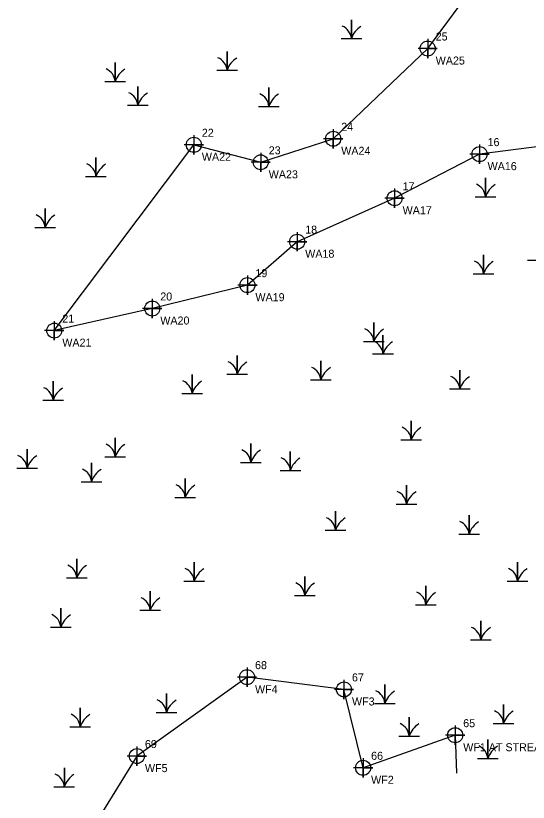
# Model space of a CAD drawing. Extents: x 2189822 to 2190837, y 387253 to 388663.
# Drawn here: x 2190174.5 to 2190334.4, y 387891.4 to 388136.9 of the extents above; entities that cross this region are included whole.
import ezdxf

# ---------------------------------------------------------------- set-up
doc = ezdxf.new("R2010")
doc.units = 0
for name, color, linetype in [('COGO Default Chain', 7, 'Continuous'), ('DTM Contours Major', 7, 'Continuous'), ('DTM Contours Minor', 7, 'Continuous'), ('Exist DTM Breakline Cogo Elevation', 7, 'Continuous'), ('Exist DTM Breakline Cogo Number', 7, 'Continuous')]:
    doc.layers.add(name, color=color, linetype=linetype)

msp = doc.modelspace()

# ---------------------------------------------------------------- linework, layer by layer
at = {"layer": 'DTM Contours Major'}
for points in [[(2190303.02, 388129.66), (2190303.02, 388123.66), (2190303.02, 388126.66), (2190306.02, 388126.66), (2190300.02, 388126.66)], [(2190273.55, 388101.49), (2190273.55, 388095.49), (2190273.55, 388098.49), (2190276.55, 388098.49), (2190270.55, 388098.49)], [(2190230.07, 388099.61), (2190230.07, 388093.61), (2190230.07, 388096.61), (2190233.07, 388096.61), (2190227.07, 388096.61)], [(2190319.2, 388096.69), (2190319.2, 388090.69), (2190319.2, 388093.69), (2190322.2, 388093.69), (2190316.2, 388093.69)], [(2190250.93, 388094.14), (2190250.93, 388088.14), (2190250.93, 388091.14), (2190253.93, 388091.14), (2190247.93, 388091.14)], [(2190292.7, 388082.93), (2190292.7, 388076.93), (2190292.7, 388079.93), (2190295.7, 388079.93), (2190289.7, 388079.93)], [(2190262.31, 388069.36), (2190262.31, 388063.36), (2190262.31, 388066.36), (2190265.31, 388066.36), (2190259.31, 388066.36)], [(2190246.78, 388055.8), (2190246.78, 388049.8), (2190246.78, 388052.8), (2190249.78, 388052.8), (2190243.78, 388052.8)], [(2190217.1, 388048.51), (2190217.1, 388042.51), (2190217.1, 388045.51), (2190220.1, 388045.51), (2190214.1, 388045.51)], [(2190186.53, 388041.61), (2190186.53, 388035.61), (2190186.53, 388038.61), (2190189.53, 388038.61), (2190183.53, 388038.61)], [(2190246.66, 387933.44), (2190246.66, 387927.44), (2190246.66, 387930.44), (2190249.66, 387930.44), (2190243.66, 387930.44)], [(2190276.9, 387929.61), (2190276.9, 387923.61), (2190276.9, 387926.61), (2190279.9, 387926.61), (2190273.9, 387926.61)], [(2190311.6, 387915.32), (2190311.6, 387909.32), (2190311.6, 387912.32), (2190314.6, 387912.32), (2190308.6, 387912.32)], [(2190212.31, 387908.81), (2190212.31, 387902.81), (2190212.31, 387905.81), (2190215.31, 387905.81), (2190209.31, 387905.81)], [(2190282.87, 387905.15), (2190282.87, 387899.15), (2190282.87, 387902.15), (2190285.87, 387902.15), (2190279.87, 387902.15)]]:
    msp.add_lwpolyline(points, dxfattribs=at)
for centre in [(2190303.02, 388126.66), (2190273.55, 388098.49), (2190230.07, 388096.61), (2190319.2, 388093.69), (2190250.93, 388091.14), (2190292.7, 388079.93), (2190262.31, 388066.36), (2190246.78, 388052.8), (2190217.1, 388045.51), (2190186.53, 388038.61), (2190246.66, 387930.44), (2190276.9, 387926.61), (2190311.6, 387912.32), (2190212.31, 387905.81), (2190282.87, 387902.15)]:
    msp.add_circle(centre, 2.34, dxfattribs=at)
at = {"layer": 'Exist DTM Breakline Cogo Elevation'}
for p, q in [((2190279.21, 388132.42), (2190279.21, 388132.42)), ((2190240.43, 388122.54), (2190240.43, 388122.54)), ((2190205.53, 388119.01), (2190205.53, 388119.01)), ((2190212.58, 388111.61), (2190212.58, 388111.61)), ((2190253.47, 388111.25), (2190253.47, 388111.25)), ((2190199.54, 388089.38), (2190199.54, 388089.38)), ((2190321.04, 388083.01), (2190321.04, 388083.01)), ((2190183.67, 388073.51), (2190183.67, 388073.51)), ((2190320.45, 388059.05), (2190320.45, 388059.05)), ((2190286.26, 388037.88), (2190286.26, 388037.88)), ((2190289.08, 388034), (2190289.08, 388034)), ((2190243.6, 388027.65), (2190243.6, 388027.65)), ((2190269.69, 388025.89), (2190269.69, 388025.89)), ((2190229.5, 388021.65), (2190229.5, 388021.65)), ((2190313.05, 388023.06), (2190313.05, 388023.06)), ((2190186.14, 388019.54), (2190186.14, 388019.54)), ((2190297.89, 388007.19), (2190297.89, 388007.19)), ((2190205.53, 388001.9), (2190205.53, 388001.9)), ((2190247.83, 388000.14), (2190247.83, 388000.14)), ((2190178.03, 387998.37), (2190178.03, 387998.37)), ((2190260.17, 387997.67), (2190260.17, 387997.67)), ((2190198.13, 387994.14), (2190198.13, 387994.14)), ((2190227.39, 387989.2), (2190227.39, 387989.2)), ((2190296.38, 387987.14), (2190296.38, 387987.14)), ((2190274.27, 387978.97), (2190274.27, 387978.97)), ((2190315.92, 387977.8), (2190315.92, 387977.8)), ((2190193.55, 387964.16), (2190193.55, 387964.16)), ((2190230.21, 387963.1), (2190230.21, 387963.1)), ((2190331.03, 387963.1), (2190331.03, 387963.1)), ((2190264.7, 387958.62), (2190264.7, 387958.62)), ((2190302.48, 387955.69), (2190302.48, 387955.69)), ((2190216.46, 387953.99), (2190216.46, 387953.99)), ((2190188.57, 387948.7), (2190188.57, 387948.7)), ((2190319.56, 387944.74), (2190319.56, 387944.74)), ((2190289.68, 387924.9), (2190289.68, 387924.9)), ((2190221.51, 387922.07), (2190221.51, 387922.07)), ((2190326.69, 387918.67), (2190326.69, 387918.67)), ((2190194.6, 387917.59), (2190194.6, 387917.59)), ((2190297.23, 387914.7), (2190297.23, 387914.7)), ((2190321.78, 387907.71), (2190321.78, 387907.71)), ((2190189.67, 387898.9), (2190189.67, 387898.9))]:
    msp.add_line(p, q, dxfattribs=at)
for points in [[(2190275.98, 388129.74), (2190279.21, 388129.74), (2190279.21, 388135.66), (2190279.21, 388129.74), (2190282.44, 388129.74)], [(2190237.21, 388119.87), (2190240.43, 388119.87), (2190240.43, 388125.78), (2190240.43, 388119.87), (2190243.66, 388119.87)], [(2190202.31, 388116.34), (2190205.53, 388116.34), (2190205.53, 388122.26), (2190205.53, 388116.34), (2190208.76, 388116.34)], [(2190209.36, 388108.93), (2190212.58, 388108.93), (2190212.58, 388114.85), (2190212.58, 388108.93), (2190215.81, 388108.93)], [(2190250.25, 388108.58), (2190253.48, 388108.58), (2190253.48, 388114.5), (2190253.48, 388108.58), (2190256.7, 388108.58)], [(2190196.31, 388086.71), (2190199.54, 388086.71), (2190199.54, 388092.63), (2190199.54, 388086.71), (2190202.76, 388086.71)], [(2190317.82, 388080.34), (2190321.04, 388080.34), (2190321.04, 388086.26), (2190321.04, 388080.34), (2190324.27, 388080.34)], [(2190180.45, 388070.83), (2190183.68, 388070.83), (2190183.68, 388076.75), (2190183.68, 388070.83), (2190186.9, 388070.83)], [(2190334.15, 388060.6), (2190337.38, 388060.6), (2190337.38, 388066.52), (2190337.38, 388060.6), (2190340.6, 388060.6)], [(2190317.23, 388056.37), (2190320.46, 388056.37), (2190320.46, 388062.29), (2190320.46, 388056.37), (2190323.68, 388056.37)], [(2190283.03, 388035.21), (2190286.26, 388035.21), (2190286.26, 388041.12), (2190286.26, 388035.21), (2190289.49, 388035.21)], [(2190285.85, 388031.33), (2190289.08, 388031.33), (2190289.08, 388037.24), (2190289.08, 388031.33), (2190292.31, 388031.33)], [(2190240.38, 388024.98), (2190243.6, 388024.98), (2190243.6, 388030.89), (2190243.6, 388024.98), (2190246.83, 388024.98)], [(2190266.47, 388023.21), (2190269.69, 388023.21), (2190269.69, 388029.13), (2190269.69, 388023.21), (2190272.92, 388023.21)], [(2190309.83, 388020.39), (2190313.05, 388020.39), (2190313.05, 388026.31), (2190313.05, 388020.39), (2190316.28, 388020.39)], [(2190226.28, 388018.98), (2190229.5, 388018.98), (2190229.5, 388024.9), (2190229.5, 388018.98), (2190232.73, 388018.98)], [(2190182.92, 388016.86), (2190186.14, 388016.86), (2190186.14, 388022.78), (2190186.14, 388016.86), (2190189.37, 388016.86)], [(2190294.67, 388004.52), (2190297.89, 388004.52), (2190297.89, 388010.43), (2190297.89, 388004.52), (2190301.12, 388004.52)], [(2190202.31, 387999.23), (2190205.53, 387999.23), (2190205.53, 388005.14), (2190205.53, 387999.23), (2190208.76, 387999.23)], [(2190174.81, 387995.7), (2190178.03, 387995.7), (2190178.03, 388001.62), (2190178.03, 387995.7), (2190181.26, 387995.7)], [(2190244.61, 387997.46), (2190247.83, 387997.46), (2190247.83, 388003.38), (2190247.83, 387997.46), (2190251.06, 387997.46)], [(2190256.95, 387994.99), (2190260.17, 387994.99), (2190260.17, 388000.91), (2190260.17, 387994.99), (2190263.4, 387994.99)], [(2190194.9, 387991.46), (2190198.13, 387991.46), (2190198.13, 387997.38), (2190198.13, 387991.46), (2190201.35, 387991.46)], [(2190224.16, 387986.53), (2190227.39, 387986.53), (2190227.39, 387992.44), (2190227.39, 387986.53), (2190230.61, 387986.53)], [(2190293.16, 387984.46), (2190296.38, 387984.46), (2190296.38, 387990.38), (2190296.38, 387984.46), (2190299.61, 387984.46)], [(2190271.05, 387976.3), (2190274.27, 387976.3), (2190274.27, 387982.21), (2190274.27, 387976.3), (2190277.5, 387976.3)], [(2190312.7, 387975.12), (2190315.92, 387975.12), (2190315.92, 387981.04), (2190315.92, 387975.12), (2190319.15, 387975.12)], [(2190190.32, 387961.48), (2190193.55, 387961.48), (2190193.55, 387967.4), (2190193.55, 387961.48), (2190196.77, 387961.48)], [(2190226.98, 387960.42), (2190230.21, 387960.42), (2190230.21, 387966.34), (2190230.21, 387960.42), (2190233.43, 387960.42)], [(2190327.81, 387960.42), (2190331.03, 387960.42), (2190331.03, 387966.34), (2190331.03, 387960.42), (2190334.26, 387960.42)], [(2190261.48, 387955.95), (2190264.7, 387955.95), (2190264.7, 387961.87), (2190264.7, 387955.95), (2190267.93, 387955.95)], [(2190299.25, 387953.01), (2190302.48, 387953.01), (2190302.48, 387958.93), (2190302.48, 387953.01), (2190305.7, 387953.01)], [(2190213.23, 387951.32), (2190216.46, 387951.32), (2190216.46, 387957.24), (2190216.46, 387951.32), (2190219.68, 387951.32)], [(2190185.35, 387946.03), (2190188.57, 387946.03), (2190188.57, 387951.95), (2190188.57, 387946.03), (2190191.8, 387946.03)], [(2190316.33, 387942.06), (2190319.56, 387942.06), (2190319.56, 387947.98), (2190319.56, 387942.06), (2190322.78, 387942.06)], [(2190286.45, 387922.23), (2190289.68, 387922.23), (2190289.68, 387928.14), (2190289.68, 387922.23), (2190292.9, 387922.23)], [(2190218.29, 387919.39), (2190221.51, 387919.39), (2190221.51, 387925.31), (2190221.51, 387919.39), (2190224.74, 387919.39)], [(2190191.38, 387914.92), (2190194.6, 387914.92), (2190194.6, 387920.84), (2190194.6, 387914.92), (2190197.83, 387914.92)], [(2190323.46, 387915.99), (2190326.69, 387915.99), (2190326.69, 387921.91), (2190326.69, 387915.99), (2190329.91, 387915.99)], [(2190294.01, 387912.02), (2190297.23, 387912.02), (2190297.23, 387917.94), (2190297.23, 387912.02), (2190300.46, 387912.02)], [(2190318.55, 387905.03), (2190321.78, 387905.03), (2190321.78, 387910.95), (2190321.78, 387905.03), (2190325, 387905.03)], [(2190186.44, 387896.22), (2190189.67, 387896.22), (2190189.67, 387902.14), (2190189.67, 387896.22), (2190192.89, 387896.22)]]:
    msp.add_lwpolyline(points, dxfattribs=at)
for centre, radius, start, end in [((2190274.61, 388129.41), 4.61, 4.1403, 67.535), ((2190286.05, 388127.47), 7.21, 122.1274, 161.6222), ((2190235.83, 388119.53), 4.61, 4.1403, 67.535), ((2190247.27, 388117.59), 7.21, 122.1274, 161.6222), ((2190200.93, 388116.01), 4.61, 4.1403, 67.535), ((2190212.37, 388114.07), 7.21, 122.1274, 161.6222), ((2190207.98, 388108.6), 4.61, 4.1403, 67.535), ((2190219.42, 388106.66), 7.21, 122.1274, 161.6222), ((2190248.88, 388108.25), 4.61, 4.1403, 67.535), ((2190260.32, 388106.31), 7.21, 122.1274, 161.6222), ((2190194.94, 388086.37), 4.61, 4.1403, 67.535), ((2190206.38, 388084.43), 7.21, 122.1274, 161.6222), ((2190316.44, 388080.01), 4.61, 4.1403, 67.535), ((2190327.88, 388078.07), 7.21, 122.1274, 161.6222), ((2190179.08, 388070.5), 4.61, 4.1403, 67.535), ((2190190.52, 388068.56), 7.21, 122.1274, 161.6222), ((2190315.86, 388056.04), 4.61, 4.1403, 67.535), ((2190327.3, 388054.1), 7.21, 122.1274, 161.6222), ((2190281.66, 388034.87), 4.61, 4.1403, 67.535), ((2190293.1, 388032.93), 7.21, 122.1274, 161.6222), ((2190284.48, 388030.99), 4.61, 4.1403, 67.535), ((2190295.92, 388029.05), 7.21, 122.1274, 161.6222), ((2190239, 388024.64), 4.61, 4.1403, 67.535), ((2190250.45, 388022.7), 7.21, 122.1274, 161.6222), ((2190265.09, 388022.88), 4.61, 4.1403, 67.535), ((2190276.53, 388020.94), 7.21, 122.1274, 161.6222), ((2190308.45, 388020.06), 4.61, 4.1403, 67.535), ((2190319.89, 388018.12), 7.21, 122.1274, 161.6222), ((2190224.9, 388018.65), 4.61, 4.1403, 67.535), ((2190236.34, 388016.71), 7.21, 122.1274, 161.6222), ((2190181.54, 388016.53), 4.61, 4.1403, 67.535), ((2190192.98, 388014.59), 7.21, 122.1274, 161.6222), ((2190293.29, 388004.18), 4.61, 4.1403, 67.535), ((2190304.73, 388002.24), 7.21, 122.1274, 161.6222), ((2190200.93, 387998.89), 4.61, 4.1403, 67.535), ((2190212.37, 387996.95), 7.21, 122.1274, 161.6222), ((2190173.44, 387995.36), 4.61, 4.1403, 67.535), ((2190184.88, 387993.42), 7.21, 122.1274, 161.6222), ((2190243.23, 387997.13), 4.61, 4.1403, 67.535), ((2190254.68, 387995.19), 7.21, 122.1274, 161.6222), ((2190255.57, 387994.66), 4.61, 4.1403, 67.535), ((2190267.01, 387992.72), 7.21, 122.1274, 161.6222), ((2190193.53, 387991.13), 4.61, 4.1403, 67.535), ((2190204.97, 387989.19), 7.21, 122.1274, 161.6222), ((2190222.79, 387986.19), 4.61, 4.1403, 67.535), ((2190234.23, 387984.25), 7.21, 122.1274, 161.6222), ((2190291.78, 387984.13), 4.61, 4.1403, 67.535), ((2190303.22, 387982.19), 7.21, 122.1274, 161.6222), ((2190269.67, 387975.96), 4.61, 4.1403, 67.535), ((2190281.12, 387974.02), 7.21, 122.1274, 161.6222), ((2190311.32, 387974.79), 4.61, 4.1403, 67.535), ((2190322.76, 387972.85), 7.21, 122.1274, 161.6222), ((2190188.95, 387961.15), 4.61, 4.1403, 67.535), ((2190200.39, 387959.21), 7.21, 122.1274, 161.6222), ((2190225.61, 387960.09), 4.61, 4.1403, 67.535), ((2190237.05, 387958.15), 7.21, 122.1274, 161.6222), ((2190326.43, 387960.09), 4.61, 4.1403, 67.535), ((2190337.87, 387958.15), 7.21, 122.1274, 161.6222), ((2190260.1, 387955.61), 4.61, 4.1403, 67.535), ((2190271.54, 387953.68), 7.21, 122.1274, 161.6222), ((2190211.86, 387950.99), 4.61, 4.1403, 67.535), ((2190223.3, 387949.05), 7.21, 122.1274, 161.6222), ((2190297.88, 387952.68), 4.61, 4.1403, 67.535), ((2190309.32, 387950.74), 7.21, 122.1274, 161.6222), ((2190183.97, 387945.7), 4.61, 4.1403, 67.535), ((2190195.41, 387943.76), 7.21, 122.1274, 161.6222), ((2190314.96, 387941.73), 4.61, 4.1403, 67.535), ((2190326.4, 387939.79), 7.21, 122.1274, 161.6222), ((2190285.08, 387921.89), 4.61, 4.1403, 67.535), ((2190296.52, 387919.95), 7.21, 122.1274, 161.6222), ((2190216.91, 387919.06), 4.61, 4.1403, 67.535), ((2190228.35, 387917.12), 7.21, 122.1274, 161.6222), ((2190190, 387914.58), 4.61, 4.1403, 67.535), ((2190201.44, 387912.64), 7.21, 122.1274, 161.6222), ((2190322.09, 387915.66), 4.61, 4.1403, 67.535), ((2190333.53, 387913.72), 7.21, 122.1274, 161.6222), ((2190292.63, 387911.69), 4.61, 4.1403, 67.535), ((2190304.07, 387909.75), 7.21, 122.1274, 161.6222), ((2190317.18, 387904.7), 4.61, 4.1403, 67.535), ((2190328.62, 387902.76), 7.21, 122.1274, 161.6222), ((2190185.07, 387895.89), 4.61, 4.1403, 67.535), ((2190196.51, 387893.95), 7.21, 122.1274, 161.6222)]:
    msp.add_arc(centre, radius, start, end, dxfattribs=at)
at = {"layer": 'Exist DTM Breakline Cogo Number'}
msp.add_line((2190311.6, 387912.32), (2190312.01, 387900.48), dxfattribs=at)
for points in [[(2190352.44, 388097.93), (2190319.2, 388093.69), (2190292.7, 388079.93), (2190262.31, 388066.36), (2190246.78, 388052.8), (2190217.1, 388045.51), (2190186.53, 388038.61), (2190230.07, 388096.61), (2190250.93, 388091.14), (2190273.55, 388098.49), (2190303.02, 388126.66), (2190317.29, 388145.97)], [(2190311.6, 387912.32), (2190282.87, 387902.15), (2190276.9, 387926.61), (2190246.66, 387930.44), (2190212.31, 387905.81), (2190187.82, 387866.13), (2190141.4, 387841.78), (2190098.41, 387819.25)]]:
    msp.add_lwpolyline(points, dxfattribs=at)

# ---------------------------------------------------------------- texts
at = {"layer": 'COGO Default Chain'}
for s, p in [('WA25', (2190305.52, 388121.66)), ('WA24', (2190276.05, 388093.49)), ('WA22', (2190232.57, 388091.61)), ('WA16', (2190321.7, 388088.69)), ('WA23', (2190253.43, 388086.14)), ('WA17', (2190295.2, 388074.93)), ('WA18', (2190264.81, 388061.36)), ('WA19', (2190249.28, 388047.8)), ('WA20', (2190219.6, 388040.51)), ('WA21', (2190189.03, 388033.61)), ('WF4', (2190249.16, 387925.44)), ('WF3', (2190279.4, 387921.61)), ('WF1 AT STREAM', (2190314.1, 387907.32)), ('WF5', (2190214.81, 387900.81)), ('WF2', (2190285.37, 387897.15))]:
    msp.add_text(s, height=2.5, dxfattribs=at).set_placement(p)
at = {"layer": 'DTM Contours Minor'}
for s, p in [('25', (2190305.52, 388129.16)), ('24', (2190276.05, 388100.99)), ('22', (2190232.57, 388099.11)), ('16', (2190321.7, 388096.19)), ('23', (2190253.43, 388093.64)), ('17', (2190295.2, 388082.43)), ('18', (2190264.81, 388068.86)), ('19', (2190249.28, 388055.3)), ('20', (2190219.6, 388048.01)), ('21', (2190189.03, 388041.11)), ('68', (2190249.16, 387932.94)), ('67', (2190279.4, 387929.11)), ('65', (2190314.1, 387914.82)), ('69', (2190214.81, 387908.31)), ('66', (2190285.37, 387904.65))]:
    msp.add_text(s, height=2.5, dxfattribs=at).set_placement(p)

doc.saveas('drawing.dxf')
